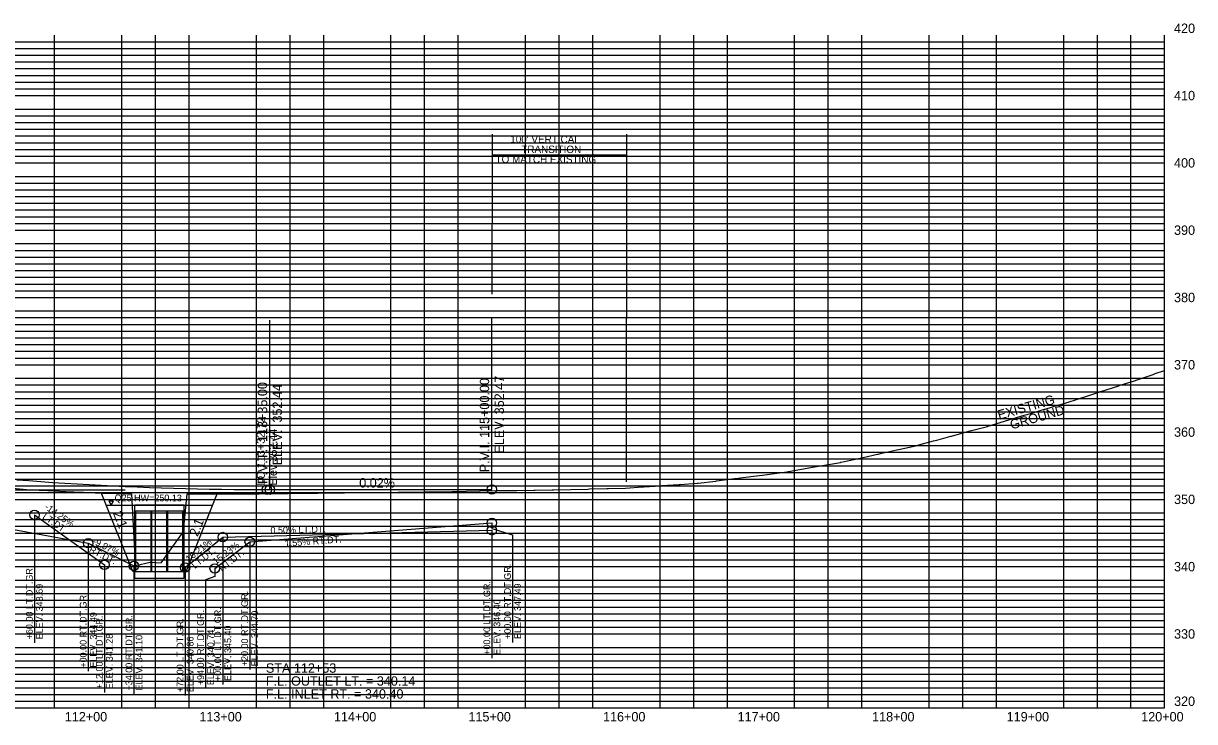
# Model space of a CAD drawing. Extents: x 1627557 to 1636561, y 783843 to 794002.
# Drawn here: x 1635691 to 1636561, y 785820 to 786339 of the extents above; entities that cross this region are included whole.
import ezdxf

# ---------------------------------------------------------------- set-up
doc = ezdxf.new("R2010")
doc.units = 0
for name, color, linetype in [('R_Axis', 7, 'Continuous'), ('R_Axis Annot', 7, 'Continuous'), ('R_Culvert', 7, 'Continuous'), ('R_Exist Surface', 7, 'Continuous'), ('R_Fin Surface', 7, 'Continuous'), ('R_Grid', 7, 'Continuous'), ('R_Profile Annot', 7, 'Continuous'), ('R_Vert Alg', 7, 'Continuous'), ('R_Vert Alg Annot', 7, 'Continuous'), ('R_Vert Alg LP', 7, 'Continuous'), ('R_Vert Alg LP Annot', 7, 'Continuous'), ('R_Vert Ditch Alg', 7, 'Continuous'), ('R_Vert Ditch Alg Annot', 7, 'Continuous'), ('RC Box Annot', 7, 'Continuous'), ('TEXT', 7, 'Continuous'), ('Transition Dimensions', 7, 'Continuous')]:
    doc.layers.add(name, color=color, linetype=linetype)

msp = doc.modelspace()

# ---------------------------------------------------------------- linework, layer by layer
at = {"layer": 'R_Axis'}
for p, q in [((1636538.9, 785830.2), (1636538.9, 786330.2)), ((1635038.9, 785830.2), (1636538.9, 785830.2))]:
    msp.add_line(p, q, dxfattribs=at)
at = {"layer": 'R_Culvert'}
for p, q in [((1635752.28, 785980.85), (1635831.37, 785980.85)), ((1635773.49, 785931.58), (1635773.49, 785981.16)), ((1635773.49, 785981.16), (1635810.16, 785981.16)), ((1635773.49, 785976.58), (1635810.16, 785976.58)), ((1635774.4, 785931.58), (1635774.4, 785976.58)), ((1635785.57, 785931.58), (1635785.57, 785976.58)), ((1635786.24, 785931.58), (1635786.24, 785976.58)), ((1635797.41, 785931.58), (1635797.41, 785976.58)), ((1635798.08, 785931.58), (1635798.08, 785976.58)), ((1635809.25, 785931.58), (1635809.25, 785976.58)), ((1635810.16, 785931.58), (1635810.16, 785981.16)), ((1635773.49, 785931.58), (1635810.16, 785931.58)), ((1635773.49, 785926.58), (1635773.49, 785931.58)), ((1635773.49, 785926.58), (1635810.16, 785926.58)), ((1635810.16, 785926.58), (1635810.16, 785931.58))]:
    msp.add_line(p, q, dxfattribs=at)
msp.add_lwpolyline([(1635756.05, 785980.86), (1635757.78, 785983.86), (1635754.32, 785983.86)], close=True, dxfattribs=at)
at = {"layer": 'R_Exist Surface'}
msp.add_lwpolyline([(1635682.77, 785993.4), (1635695.51, 785992.32), (1635695.71, 785992.31), (1635708.82, 785991.69), (1635708.94, 785991.69), (1635722.13, 785991.07), (1635722.17, 785991.07), (1635722.2, 785991.07), (1635728.25, 785990.79), (1635735.35, 785990.45), (1635735.4, 785990.44), (1635748.5, 785989.82), (1635748.64, 785989.81), (1635770.88, 785989.24), (1635771.17, 785989.24), (1635773.88, 785937.63), (1635773.94, 785936.12), (1635773.96, 785936.12), (1635774.22, 785936.13), (1635784.84, 785938.64), (1635793.03, 785937.93), (1635809.18, 785960.63), (1635809.51, 785960.81), (1635809.68, 785961.64), (1635809.77, 785961.87), (1635812.39, 785989.32), (1635825.57, 785989.34), (1635825.77, 785989.34), (1635838.98, 785989.36), (1635839.15, 785989.36), (1635839.32, 785989.36), (1635852.54, 785989.38), (1635852.67, 785989.38), (1635865.92, 785989.4), (1635866.03, 785989.4), (1635887.65, 785989.65), (1635887.72, 785989.65), (1635909.43, 785989.9), (1635909.45, 785989.9), (1635909.47, 785989.9), (1635912.73, 785989.94), (1635929.35, 785990.1), (1635929.43, 785990.1), (1635949.15, 785990.28), (1635949.34, 785990.29), (1635949.52, 785990.29), (1635969.14, 785990.47), (1635969.43, 785990.48), (1635988.85, 785990.66), (1635989.25, 785990.67), (1635989.64, 785990.67), (1636009.5, 785991.09), (1636009.93, 785991.1), (1636029.7, 785991.52), (1636030.18, 785991.52), (1636043.06, 785991.68), (1636043.76, 785991.69), (1636056.58, 785991.85), (1636057.38, 785991.86), (1636070.14, 785992.02), (1636071.04, 785992.04), (1636083.73, 785992.19), (1636084.74, 785992.22), (1636097.54, 785992.56), (1636110.25, 785992.89), (1636111.57, 785992.92), (1636124.26, 785993.26), (1636125.65, 785993.29), (1636138.31, 785993.62), (1636150.86, 785994.45), (1636151.78, 785994.51), (1636164.4, 785995.34), (1636165.25, 785995.39), (1636177.94, 785996.23), (1636178.72, 785996.28), (1636191.47, 785997.13), (1636192.18, 785997.17), (1636205.37, 785998.83), (1636205.88, 785998.89), (1636219.28, 786000.59), (1636219.59, 786000.62), (1636219.89, 786000.66), (1636233.3, 786002.36), (1636233.4, 786002.37), (1636240.02, 786003.21), (1636247.01, 786004.07), (1636247.08, 786004.08), (1636256.29, 786005.31), (1636256.75, 786005.4), (1636278.64, 786009.25), (1636298.07, 786012.67), (1636298.26, 786012.71), (1636301.04, 786013.24), (1636312.61, 786015.8), (1636314.82, 786016.33), (1636325.53, 786018.7), (1636325.94, 786018.8), (1636328.61, 786019.44), (1636339.82, 786021.91), (1636342.39, 786022.54), (1636352.8, 786024.83), (1636353.74, 786025.03), (1636356.17, 786025.61), (1636367.21, 786028.62), (1636369.57, 786029.27), (1636380.07, 786032.13), (1636380.54, 786032.25), (1636382.98, 786032.92), (1636394.42, 786035.99), (1636396.37, 786036.52), (1636407.33, 786039.45), (1636408.34, 786039.72), (1636409.77, 786040.1), (1636411.08, 786040.52), (1636423.19, 786044.19), (1636434.6, 786047.65), (1636435.46, 786047.91), (1636436.62, 786048.27), (1636449.54, 786052.11), (1636450.04, 786052.26), (1636460.39, 786055.33), (1636461.87, 786055.76), (1636463.26, 786056.14), (1636463.45, 786056.19), (1636477.01, 786060.67), (1636477.25, 786060.75), (1636489.14, 786064.66), (1636490.72, 786065.16), (1636491.05, 786065.27), (1636491.42, 786065.39), (1636504.84, 786069.64), (1636505.83, 786069.96), (1636516.41, 786073.31), (1636518.59, 786073.97), (1636530.39, 786078.09), (1636531.79, 786078.59), (1636538.9, 786081.06)], dxfattribs=at)
at = {"layer": 'R_Fin Surface'}
for p, q in [((1635811.66, 785931.58), (1635834.78, 785989.36)), ((1635810.16, 785931.58), (1635811.66, 785931.58))]:
    msp.add_line(p, q, dxfattribs=at)
msp.add_lwpolyline([(1635773.49, 785931.58), (1635771.99, 785931.58), (1635748.53, 785990.21)], dxfattribs=at)
at = {"layer": 'R_Grid'}
for p, q in [((1635038.9, 786325.2), (1636538.9, 786325.2)), ((1635713.9, 785830.2), (1635713.9, 786330.2)), ((1635763.9, 785830.2), (1635763.9, 786330.2)), ((1635788.9, 785830.2), (1635788.9, 786330.2)), ((1635813.9, 785830.2), (1635813.9, 786330.2)), ((1635863.9, 785830.2), (1635863.9, 786330.2)), ((1635888.9, 785830.2), (1635888.9, 786330.2)), ((1635913.9, 785830.2), (1635913.9, 786330.2)), ((1635963.9, 785830.2), (1635963.9, 786330.2)), ((1635988.9, 785830.2), (1635988.9, 786330.2)), ((1636013.9, 785830.2), (1636013.9, 786330.2)), ((1636063.9, 785830.2), (1636063.9, 786330.2)), ((1636088.9, 785830.2), (1636088.9, 786330.2)), ((1636113.9, 785830.2), (1636113.9, 786330.2)), ((1636163.9, 785830.2), (1636163.9, 786330.2)), ((1636188.9, 785830.2), (1636188.9, 786330.2)), ((1636213.9, 785830.2), (1636213.9, 786330.2)), ((1636263.9, 785830.2), (1636263.9, 786330.2)), ((1636288.9, 785830.2), (1636288.9, 786330.2)), ((1636313.9, 785830.2), (1636313.9, 786330.2)), ((1636363.9, 785830.2), (1636363.9, 786330.2)), ((1636388.9, 785830.2), (1636388.9, 786330.2)), ((1636413.9, 785830.2), (1636413.9, 786330.2)), ((1636463.9, 785830.2), (1636463.9, 786330.2)), ((1636488.9, 785830.2), (1636488.9, 786330.2)), ((1636513.9, 785830.2), (1636513.9, 786330.2)), ((1635038.9, 786320.2), (1636538.9, 786320.2)), ((1635038.9, 786315.2), (1636538.9, 786315.2)), ((1635038.9, 786310.2), (1636538.9, 786310.2)), ((1635038.9, 786305.2), (1636538.9, 786305.2)), ((1635038.9, 786300.2), (1636538.9, 786300.2)), ((1635038.9, 786295.2), (1636538.9, 786295.2)), ((1635038.9, 786290.2), (1636538.9, 786290.2)), ((1635038.9, 786285.2), (1636538.9, 786285.2)), ((1635038.9, 786275.2), (1636538.9, 786275.2)), ((1635038.9, 786270.2), (1636538.9, 786270.2)), ((1635038.9, 786265.2), (1636538.9, 786265.2)), ((1635038.9, 786260.2), (1636538.9, 786260.2)), ((1635038.9, 786255.2), (1636538.9, 786255.2)), ((1635038.9, 786250.2), (1636538.9, 786250.2)), ((1635038.9, 786245.2), (1636538.9, 786245.2)), ((1635038.9, 786240.2), (1636538.9, 786240.2)), ((1635038.9, 786235.2), (1636538.9, 786235.2)), ((1635038.9, 786225.2), (1636538.9, 786225.2)), ((1635038.9, 786220.2), (1636538.9, 786220.2)), ((1635038.9, 786215.2), (1636538.9, 786215.2)), ((1635038.9, 786210.2), (1636538.9, 786210.2)), ((1635038.9, 786205.2), (1636538.9, 786205.2)), ((1635038.9, 786200.2), (1636538.9, 786200.2)), ((1635038.9, 786195.2), (1636538.9, 786195.2)), ((1635038.9, 786190.2), (1636538.9, 786190.2)), ((1635038.9, 786185.2), (1636538.9, 786185.2)), ((1635038.9, 786175.2), (1636538.9, 786175.2)), ((1635038.9, 786170.2), (1636538.9, 786170.2)), ((1635038.9, 786165.2), (1636538.9, 786165.2)), ((1635038.9, 786160.2), (1636538.9, 786160.2)), ((1635038.9, 786155.2), (1636538.9, 786155.2)), ((1635038.9, 786150.2), (1636538.9, 786150.2)), ((1635038.9, 786145.2), (1636538.9, 786145.2)), ((1635038.9, 786140.2), (1636538.9, 786140.2)), ((1635038.9, 786135.2), (1636538.9, 786135.2)), ((1635038.9, 786125.2), (1636538.9, 786125.2)), ((1635038.9, 786120.2), (1636538.9, 786120.2)), ((1635038.9, 786115.2), (1636538.9, 786115.2)), ((1635038.9, 786110.2), (1636538.9, 786110.2)), ((1635038.9, 786105.2), (1636538.9, 786105.2)), ((1635038.9, 786100.2), (1636538.9, 786100.2)), ((1635038.9, 786095.2), (1636538.9, 786095.2)), ((1635038.9, 786090.2), (1636538.9, 786090.2)), ((1635038.9, 786085.2), (1636538.9, 786085.2)), ((1635038.9, 786075.2), (1636538.9, 786075.2)), ((1635038.9, 786070.2), (1636538.9, 786070.2)), ((1635038.9, 786065.2), (1636538.9, 786065.2)), ((1635038.9, 786060.2), (1636538.9, 786060.2)), ((1635038.9, 786055.2), (1636538.9, 786055.2)), ((1635038.9, 786050.2), (1636538.9, 786050.2)), ((1635038.9, 786045.2), (1636538.9, 786045.2)), ((1635038.9, 786040.2), (1636538.9, 786040.2)), ((1635038.9, 786035.2), (1636538.9, 786035.2)), ((1635038.9, 786025.2), (1636538.9, 786025.2)), ((1635038.9, 786020.2), (1636538.9, 786020.2)), ((1635038.9, 786015.2), (1636538.9, 786015.2)), ((1635038.9, 786010.2), (1636538.9, 786010.2)), ((1635038.9, 786005.2), (1636538.9, 786005.2)), ((1635038.9, 786000.2), (1636538.9, 786000.2)), ((1635038.9, 785995.2), (1636538.9, 785995.2)), ((1635038.9, 785990.2), (1636538.9, 785990.2)), ((1635038.9, 785985.2), (1636538.9, 785985.2)), ((1635038.9, 785975.2), (1636538.9, 785975.2)), ((1635038.9, 785970.2), (1636538.9, 785970.2)), ((1635038.9, 785965.2), (1636538.9, 785965.2)), ((1635038.9, 785960.2), (1636538.9, 785960.2)), ((1635038.9, 785955.2), (1636538.9, 785955.2)), ((1635038.9, 785950.2), (1636538.9, 785950.2)), ((1635038.9, 785945.2), (1636538.9, 785945.2)), ((1635038.9, 785940.2), (1636538.9, 785940.2)), ((1635038.9, 785935.2), (1636538.9, 785935.2)), ((1635038.9, 785925.2), (1636538.9, 785925.2)), ((1635038.9, 785920.2), (1636538.9, 785920.2)), ((1635038.9, 785915.2), (1636538.9, 785915.2)), ((1635038.9, 785910.2), (1636538.9, 785910.2)), ((1635038.9, 785905.2), (1636538.9, 785905.2)), ((1635038.9, 785900.2), (1636538.9, 785900.2)), ((1635038.9, 785895.2), (1636538.9, 785895.2)), ((1635038.9, 785890.2), (1636538.9, 785890.2)), ((1635038.9, 785885.2), (1636538.9, 785885.2)), ((1635038.9, 785875.2), (1636538.9, 785875.2)), ((1635038.9, 785870.2), (1636538.9, 785870.2)), ((1635038.9, 785865.2), (1636538.9, 785865.2)), ((1635038.9, 785860.2), (1636538.9, 785860.2)), ((1635038.9, 785855.2), (1636538.9, 785855.2)), ((1635038.9, 785850.2), (1636538.9, 785850.2)), ((1635038.9, 785845.2), (1636538.9, 785845.2)), ((1635038.9, 785840.2), (1636538.9, 785840.2)), ((1635038.9, 785835.2), (1636538.9, 785835.2))]:
    msp.add_line(p, q, dxfattribs=at)
at = {"layer": 'R_Vert Alg'}
for p, q in [((1635873.9, 785992.41), (1635873.9, 786118.41)), ((1636038.9, 785992.57), (1636038.9, 786120.63)), ((1635658.9, 785992.2), (1635766.4, 785992.3)), ((1635873.9, 785992.41), (1636038.9, 785992.57))]:
    msp.add_line(p, q, dxfattribs=at)
msp.add_lwpolyline([(1635685.78, 785999.8), (1635694.73, 785999.1), (1635703.69, 785998.44), (1635712.65, 785997.81), (1635721.61, 785997.22), (1635730.57, 785996.66), (1635739.53, 785996.14), (1635748.48, 785995.65), (1635757.44, 785995.2), (1635766.4, 785994.78), (1635775.36, 785994.39), (1635784.32, 785994.04), (1635793.28, 785993.72), (1635802.23, 785993.44), (1635811.19, 785993.19), (1635820.15, 785992.98), (1635829.11, 785992.79), (1635838.07, 785992.65), (1635847.03, 785992.54), (1635855.98, 785992.46), (1635864.94, 785992.42), (1635873.9, 785992.41)], dxfattribs=at)
for centre in [(1635873.9, 785992.41), (1636038.9, 785992.57)]:
    msp.add_circle(centre, 3.5, dxfattribs=at)
at = {"layer": 'R_Vert Alg LP'}
msp.add_circle((1635871.62, 785992.41), 3.5, dxfattribs=at)
at = {"layer": 'R_Vert Ditch Alg'}
for p, q in [((1635438.9, 786007.55), (1635738.9, 785952.65)), ((1635698.9, 785973.65), (1635698.9, 785963.65)), ((1635698.9, 785973.65), (1635750.9, 785936.6)), ((1635858.9, 785953.7), (1636038.9, 785967.65)), ((1635698.9, 785963.65), (1635698.9, 785878.65)), ((1635838.9, 785957.2), (1636038.9, 785962.2)), ((1636038.9, 785962.2), (1636038.9, 785952.2)), ((1636054.25, 785958.75), (1636054.25, 785878.94)), ((1635738.9, 785952.65), (1635738.9, 785942.65)), ((1635738.9, 785952.65), (1635772.9, 785935.7)), ((1635810.9, 785934.5), (1635838.9, 785957.2)), ((1635832.9, 785933.9), (1635858.9, 785953.7)), ((1635838.9, 785957.2), (1635838.9, 785932.7)), ((1635858.9, 785953.7), (1635858.9, 785943.7)), ((1636038.9, 785952.2), (1636038.9, 785867.2)), ((1635738.9, 785942.65), (1635738.9, 785857.65)), ((1635858.9, 785943.7), (1635858.9, 785858.7)), ((1635750.9, 785936.6), (1635750.9, 785926.6)), ((1635772.9, 785935.7), (1635772.9, 785925.7)), ((1635810.9, 785934.5), (1635810.9, 785924.5)), ((1635832.9, 785933.9), (1635832.9, 785927.78)), ((1635838.9, 785932.7), (1635838.9, 785847.7)), ((1635750.9, 785926.6), (1635750.9, 785841.6)), ((1635772.9, 785925.7), (1635772.9, 785840.7)), ((1635810.9, 785924.5), (1635810.9, 785839.5))]:
    msp.add_line(p, q, dxfattribs=at)
for points in [[(1636038.9, 785967.65), (1636038.9, 785963.62), (1636054.25, 785958.75)], [(1635832.9, 785927.78), (1635826.16, 785925.46), (1635826.16, 785844.61)]]:
    msp.add_lwpolyline(points, dxfattribs=at)
for centre in [(1635698.9, 785973.65), (1636038.9, 785967.65), (1635838.9, 785957.2), (1636038.9, 785962.2), (1635738.9, 785952.65), (1635858.9, 785953.7), (1635750.9, 785936.6), (1635772.9, 785935.7), (1635810.9, 785934.5), (1635832.9, 785933.9)]:
    msp.add_circle(centre, 3.5, dxfattribs=at)
at = {"layer": 'Transition Dimensions'}
for p, q in [((1636039.04, 786256.62), (1636039.03, 786241.24)), ((1636139.02, 786256.62), (1636139.01, 786241.24)), ((1636039.03, 786241.24), (1636038.92, 786137.68)), ((1636039.03, 786241.24), (1636139.01, 786241.24)), ((1636139.01, 786241.24), (1636138.76, 785998.12))]:
    msp.add_line(p, q, dxfattribs=at)

# ---------------------------------------------------------------- texts
at = {"layer": 'R_Axis Annot'}
for s, p in [('420', (1636545.9, 786331.7)), ('420', (1636545.9, 786331.7)), ('410', (1636545.9, 786281.7)), ('400', (1636545.9, 786231.7)), ('390', (1636545.9, 786181.7)), ('380', (1636545.9, 786131.7)), ('370', (1636545.9, 786081.7)), ('360', (1636545.9, 786031.7)), ('350', (1636545.9, 785981.7)), ('340', (1636545.9, 785931.7)), ('330', (1636545.9, 785881.7)), ('320', (1636545.9, 785831.7)), ('112+00', (1635721.49, 785820.2)), ('113+00', (1635821.49, 785820.2)), ('114+00', (1635921.49, 785820.2)), ('115+00', (1636021.49, 785820.2)), ('116+00', (1636121.5, 785820.2)), ('117+00', (1636221.49, 785820.2)), ('118+00', (1636321.49, 785820.2)), ('119+00', (1636421.49, 785820.2)), ('120+00', (1636521.49, 785820.2))]:
    msp.add_text(s, height=7, dxfattribs=at).set_placement(p)
at = {"layer": 'R_Culvert'}
msp.add_text('Q25 HW=250.13', height=5, dxfattribs=at).set_placement((1635758.49, 785983.71))
at = {"layer": 'R_Profile Annot'}
for rotation, p in [(291.80141, (1635757.15, 785974.98)), (68.19859, (1635820.19, 785957.11))]:
    msp.add_text('2:1', height=7, rotation=rotation, dxfattribs=at).set_placement(p)
at = {"layer": 'R_Vert Alg Annot'}
for s, rotation, p in [('P.V.T.  113+35.00', 90, (1635871.9, 785996.6)), ('P.V.I. 115+00.00', 90, (1636036.9, 786005.32)), ('ELEV. 352.47', 90, (1636047.9, 786019.24)), ('ELEV.  352.44', 90, (1635882.9, 786010.52)), ('0.02%', 0.05579, (1635940.3, 785993.97))]:
    msp.add_text(s, height=7, rotation=rotation, dxfattribs=at).set_placement(p)
at = {"layer": 'R_Vert Alg LP Annot'}
for s, p in [('LO 113+32.72', (1635870.12, 785995.41)), ('Elev 352.44', (1635879.12, 785995.41))]:
    msp.add_text(s, height=6, rotation=90, dxfattribs=at).set_placement(p)
at = {"layer": 'R_Vert Ditch Alg Annot'}
for s, rotation, p in [('-14.25%', 324.53013, (1635706.01, 785978.49)), ('LT.DT.', 324.53013, (1635704.48, 785971.39)), ('0.50% LT.DT.', 1.4321, (1635874.38, 785959.71)), ('RT.DT.', 333.5024, (1635739.06, 785946.3)), ('-9.97%', 333.5024, (1635741.7, 785952.43)), ('16.21%', 39.03218, (1635813.7, 785938.3)), ('15.23%', 37.29067, (1635833.8, 785936.45)), ('1.55% RT.DT.', 4.43156, (1635885.14, 785949.93)), ('LT.DT.', 39.03218, (1635818.19, 785933.36)), ('RT.DT.', 37.29067, (1635838.14, 785931.37)), ('+60.00 LT.DT.GR.', 90, (1635697.65, 785881.15)), ('+00.00 RT.DT.GR.', 90, (1636053, 785881.44)), ('+00.00 LT.DT.GR.', 90, (1636037.65, 785869.7)), ('ELEV. 348.69', 90, (1635705.15, 785881.15)), ('+00.00 RT.DT.GR.', 90, (1635737.65, 785860.15)), ('+20.00 RT.DT.GR.', 90, (1635857.65, 785861.2)), ('ELEV. 347.49', 90, (1636060.5, 785881.44)), ('ELEV. 346.40', 90, (1636045.15, 785869.7)), ('ELEV. 344.49', 90, (1635745.15, 785860.15)), ('+12.00 LT.DT.GR.', 90, (1635749.65, 785844.1)), ('+34.00 RT.DT.GR.', 90, (1635771.65, 785843.2)), ('+94.00 RT.DT.GR.', 90, (1635824.91, 785847.11)), ('+00.00 LT.DT.GR.', 90, (1635837.65, 785850.2)), ('ELEV. 344.70', 90, (1635865.15, 785861.2)), ('+72.00 LT.DT.GR.', 90, (1635809.65, 785842)), ('ELEV. 345.40', 90, (1635845.15, 785850.2)), ('ELEV. 341.28', 90, (1635757.15, 785844.1)), ('ELEV. 341.10', 90, (1635779.15, 785843.2)), ('ELEV. 340.86', 90, (1635817.15, 785842)), ('ELEV. 340.74', 90, (1635832.41, 785847.11))]:
    msp.add_text(s, height=5, rotation=rotation, dxfattribs=at).set_placement(p)
at = {"layer": 'RC Box Annot'}
for s, p in [('STA 112+53', (1635870.96, 785856.38)), ('F.L. OUTLET LT. = 340.14', (1635870.96, 785846.75)), ('F.L. INLET RT. = 340.40', (1635870.96, 785837.13))]:
    msp.add_text(s, height=7, dxfattribs=at).set_placement(p)
at = {"layer": 'TEXT'}
for s, p in [('EXISTING', (1636415.91, 786044.25)), ('GROUND', (1636425.18, 786037.06))]:
    msp.add_text(s, height=7, rotation=16.15255, dxfattribs=at).set_placement(p)
at = {"layer": 'Transition Dimensions'}
for s, p in [("100' VERTICAL", (1636052.57, 786250.03)), ('TRANSITION', (1636060.77, 786242.57)), ('TO MATCH EXISTING', (1636041.63, 786235.16))]:
    msp.add_text(s, height=5.5, rotation=359.88664, dxfattribs=at).set_placement(p)

doc.saveas('drawing.dxf')
